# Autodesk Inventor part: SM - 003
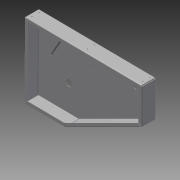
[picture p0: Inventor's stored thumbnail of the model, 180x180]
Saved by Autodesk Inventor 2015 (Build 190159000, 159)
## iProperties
Created: 2007-02
Part Number: SM - 003
Material: Steel
Document SubType Name: Sheet Metal
Designer: Autodesk, Inc.
Mass: 16124.5 g
Surface Area: 13619.8 cm^2
Volume: 2054.07 cm^3
Density: 7.85 g/cm^3
Description: Drive Casing
Sheet Metal Rule: Default
Appearance: Steel
Author: Autodesk, Inc.
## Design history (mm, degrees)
sketch "Sketch1"
  geometry: L1 (-191.283, 377.15)-(658.676, 368.784) reference; L2 (658.676, 368.784)-(656.097, 106.765); L3 (656.097, 106.765)-(102.83, -170.662); L4 (102.83, -170.662)-(-196.646, -167.714); L5 (-196.646, -167.714)-(-191.283, 377.15); L6 (-99.694, 136.47)-(-25.616, 266.858); L7 (-20.095, 263.721)-(-94.173, 133.333); L8 (-105.215, 139.606)-(-31.137, 269.995); C1 r 25.4 at (30.661, 24.948); C2 r 15.875 at (514.8, 240.763) reference; C3 r 17.145 at (514.8, 240.763); C4 r 6.35 at (190.203, 181.588); A1 r 6.35 centre (-99.694, 136.47) between (-105.215, 139.606) and (-94.173, 133.333); A2 r 6.35 centre (-25.616, 266.858) between (-20.095, 263.721) and (-31.137, 269.995); 1 further point
  constraints: 14 end point, 5 centre point, 4 point on circle, 4 tangent, 3 coincident, 2 perpendicular, 1 parallel, 1 other
  dimensions: "d0" = 1.27 radial gap between concentric circles of C3 C2; "d1" = 12.7 diameter of A2; "d2" = 12.7 diameter of A1 (= d1); "d3" = 12.7 diameter of C4
  node "Reference2"
  node "Reference3"
node "Face1"
node "Flange1"
node "Flange2"
node "Flange3"
feature "Corner4" dims "d34" = 12.192 (= CornerReliefSize), "d35" = 3.048 (= BendRadius), "d36" = 3.048 (= Thickness), "d37" = 0, "Thickness" = 3.048
node "Flange4"
feature "Corner6" dims "d49" = 12.192 (= CornerReliefSize), "d50" = 3.048 (= BendRadius), "d51" = 3.048 (= Thickness), "d52" = 0, "Thickness" = 3.048
node "Flange5"
node "Flange6"
feature "Corner9" dims "d75" = 12.192 (= CornerReliefSize), "d76" = 3.048 (= BendRadius), "d77" = 3.048 (= Thickness), "d78" = 0, "Thickness" = 3.048
feature "Corner10" dims "d79" = 12.192 (= CornerReliefSize), "d80" = 3.048 (= BendRadius), "d81" = 3.048 (= Thickness), "d82" = 0, "Thickness" = 3.048
feature "Corner11" dims "d83" = 12.192 (= CornerReliefSize), "d84" = 3.048 (= BendRadius), "d85" = 3.048 (= Thickness), "d86" = 0, "Thickness" = 3.048
hole "Hole1" diameter "d89" = 6.7564; stored, may be unused: countersink angle "d93" = 82 deg, drill point angle "d95" = 118 deg; dims "d87" = 19.05, "d88" = 19.05, "d90" = 12.7, "d91" = 11.1252, "d92" = 6.35, "d94" = 3.048 (= Thickness)
pattern_linear "Rectangular Pattern1" dims "d98" = 50.8, "d101" = 401.32
hole "Hole2" diameter "d104" = 3.683; stored, may be unused: countersink angle "d108" = 82 deg, drill point angle "d110" = 118 deg; dims "d102" = 9.525, "d103" = 25.4, "d105" = 12.7, "d106" = 9.525, "d107" = 6.35, "d109" = 3.048 (= Thickness)
hole "Hole3" diameter "d113" = 3.683; stored, may be unused: countersink angle "d117" = 82 deg, drill point angle "d119" = 118 deg; dims "d111" = 9.525, "d112" = 31.75, "d114" = 12.7, "d115" = 9.525, "d116" = 6.35, "d118" = 3.048 (= Thickness)
hole "Hole4" diameter "d122" = 3.683; stored, may be unused: countersink angle "d126" = 82 deg, drill point angle "d128" = 118 deg; dims "d120" = 9.525, "d121" = 31.75, "d123" = 12.7, "d124" = 9.525, "d125" = 6.35, "d127" = 3.048 (= Thickness)
hole "Hole5" diameter "d131" = 3.683; stored, may be unused: countersink angle "d135" = 82 deg, drill point angle "d137" = 118 deg; dims "d129" = 9.525, "d130" = 15.875, "d132" = 12.7, "d133" = 9.525, "d134" = 6.35, "d136" = 3.048 (= Thickness)
hole "Hole6" diameter "d140" = 3.683; stored, may be unused: countersink angle "d144" = 82 deg, drill point angle "d146" = 118 deg; dims "d138" = 9.525, "d139" = 31.75, "d141" = 12.7, "d142" = 9.525, "d143" = 6.35, "d145" = 3.048 (= Thickness)
pattern_linear "Rectangular Pattern2" dims "d149" = 483.4382
pattern_linear "Rectangular Pattern3" dims "d152" = 251.5362
pattern_linear "Rectangular Pattern4" dims "d155" = 574.8782
pattern_linear "Rectangular Pattern5" dims "d158" = 782.193
pattern_linear "Rectangular Pattern6" dims "d161" = 204.4954
body "Solid1"
face "Plate1" dims "Thickness" = 3.048
sketch "Sketch2"
  geometry: L1 through (-425, 0) direction (1, -7.25e-35); L2 through (0, 50.8) direction (0, 1); L3 (0, 101.6)-(-850, 101.6); L4 (-850, 101.6)-(-850, 0)
  constraints: 6 end point, 1 horizontal, 1 perpendicular, 1 vertical
face "Plate2" dims "d5" = 3.048 (= BendReliefWidth), "d6" = 1.524 (= BendReliefDepth), "d7" = 6.096 (= MinimumRemnant), "d8" = 3.048 (= BendRadius), "d9" = 101.6, "d10" = 90 deg, "d11" = 3.048 (= BendRadius), "d12" = 12.192 (= CornerReliefSize), "d13" = 3.048 (= Thickness), "d162" = 3.048 (= JacobiRadiusSize), "SeamGap" = 0.00508, "Thickness" = 3.048
bend "Bend1" dims "d5" = 3.048 (= BendReliefWidth), "d6" = 1.524 (= BendReliefDepth), "d7" = 6.096 (= MinimumRemnant), "d8" = 3.048 (= BendRadius), "d9" = 101.6, "d10" = 90 deg, "d11" = 3.048 (= BendRadius), "SeamGap" = 0.00508, "Thickness" = 3.048
feature "Corner1" dims "d9" = 101.6, "d10" = 90 deg, "d12" = 12.192 (= CornerReliefSize), "d13" = 3.048 (= Thickness), "d162" = 3.048 (= JacobiRadiusSize)
sketch "Sketch3"
  geometry: L1 through (419.776, -4.132) direction (-1, 0.00984); L2 through (-0.125, -12.699) direction (-0.00984, -1); L3 (-0.25, -25.399)-(839.303, -33.662); L4 (839.303, -33.662)-(839.553, -8.264)
  constraints: 6 end point, 1 perpendicular, 2 other
face "Plate3" dims "d14" = 3.048 (= BendReliefWidth), "d15" = 1.524 (= BendReliefDepth), "d16" = 6.096 (= MinimumRemnant), "d17" = 3.048 (= BendRadius), "d18" = 25.4, "d19" = 90 deg, "d20" = 3.048 (= BendRadius), "d21" = 12.192 (= CornerReliefSize), "d22" = 3.048 (= Thickness), "d163" = 3.048 (= JacobiRadiusSize), "SeamGap" = 0.00508, "Thickness" = 3.048
bend "Bend2" dims "d14" = 3.048 (= BendReliefWidth), "d15" = 1.524 (= BendReliefDepth), "d16" = 6.096 (= MinimumRemnant), "d17" = 3.048 (= BendRadius), "d18" = 25.4, "d19" = 90 deg, "d20" = 3.048 (= BendRadius), "SeamGap" = 0.00508, "Thickness" = 3.048
feature "Corner2" dims "d18" = 25.4, "d19" = 90 deg, "d21" = 12.192 (= CornerReliefSize), "d22" = 3.048 (= Thickness), "d163" = 3.048 (= JacobiRadiusSize)
sketch "Sketch4"
  geometry: L1 (-0.224, -22.736)-(-2.492, -253.169); L2 (-2.492, -253.169)-(-27.891, -252.919); L3 (-27.891, -252.919)-(-25.623, -22.486); L4 (-25.623, -22.486)-(-0.224, -22.736)
  constraints: 8 end point
face "Plate4" dims "d23" = 3.048 (= BendReliefWidth), "d24" = 1.524 (= BendReliefDepth), "d25" = 6.096 (= MinimumRemnant), "d26" = 3.048 (= BendRadius), "d27" = 0, "d28" = 2.54, "d29" = 25.4, "d30" = 90 deg, "d31" = 3.048 (= BendRadius), "d32" = 12.192 (= CornerReliefSize), "d33" = 3.048 (= Thickness), "d164" = 3.048 (= JacobiRadiusSize), "SeamGap" = 0.00508, "Thickness" = 3.048
bend "Bend3" dims "d23" = 3.048 (= BendReliefWidth), "d24" = 1.524 (= BendReliefDepth), "d25" = 6.096 (= MinimumRemnant), "d26" = 3.048 (= BendRadius), "d29" = 25.4, "d30" = 90 deg, "d31" = 3.048 (= BendRadius), "SeamGap" = 0.00508, "Thickness" = 3.048
feature "Corner3" dims "d29" = 25.4, "d30" = 90 deg, "d32" = 12.192 (= CornerReliefSize), "d33" = 3.048 (= Thickness), "d164" = 3.048 (= JacobiRadiusSize)
sketch "Sketch5"
  geometry: L1 (-17.717, -8.884)-(-547.946, -274.759); L2 (-547.946, -274.759)-(-559.332, -252.054); L3 (-559.332, -252.054)-(-29.102, 13.821); L4 (-29.102, 13.821)-(-17.717, -8.884)
  constraints: 8 end point
face "Plate5" dims "d38" = 3.048 (= BendReliefWidth), "d39" = 1.524 (= BendReliefDepth), "d40" = 6.096 (= MinimumRemnant), "d41" = 3.048 (= BendRadius), "d42" = 0, "d43" = 2.54, "d44" = 25.4, "d45" = 90 deg, "d46" = 3.048 (= BendRadius), "d47" = 12.192 (= CornerReliefSize), "d48" = 3.048 (= Thickness), "d165" = 3.048 (= JacobiRadiusSize), "SeamGap" = 0.00508, "Thickness" = 3.048
bend "Bend4" dims "d38" = 3.048 (= BendReliefWidth), "d39" = 1.524 (= BendReliefDepth), "d40" = 6.096 (= MinimumRemnant), "d41" = 3.048 (= BendRadius), "d44" = 25.4, "d45" = 90 deg, "d46" = 3.048 (= BendRadius), "SeamGap" = 0.00508, "Thickness" = 3.048
feature "Corner5" dims "d44" = 25.4, "d45" = 90 deg, "d47" = 12.192 (= CornerReliefSize), "d48" = 3.048 (= Thickness), "d165" = 3.048 (= JacobiRadiusSize)
sketch "Sketch6"
  geometry: L1 (-9.792, 0.096)-(-291.968, 2.874); L2 (-291.968, 2.874)-(-291.718, 28.273); L3 (-291.718, 28.273)-(-9.542, 25.495); L4 (-9.542, 25.495)-(-9.792, 0.096)
  constraints: 8 end point
face "Plate6" dims "d53" = 3.048 (= BendReliefWidth), "d54" = 1.524 (= BendReliefDepth), "d55" = 6.096 (= MinimumRemnant), "d56" = 3.048 (= BendRadius), "d57" = 0, "d58" = 2.54, "d59" = 25.4, "d60" = 90 deg, "d61" = 3.048 (= BendRadius), "d62" = 12.192 (= CornerReliefSize), "d63" = 3.048 (= Thickness), "d166" = 3.048 (= JacobiRadiusSize), "SeamGap" = 0.00508, "Thickness" = 3.048
bend "Bend5" dims "d53" = 3.048 (= BendReliefWidth), "d54" = 1.524 (= BendReliefDepth), "d55" = 6.096 (= MinimumRemnant), "d56" = 3.048 (= BendRadius), "d59" = 25.4, "d60" = 90 deg, "d61" = 3.048 (= BendRadius), "SeamGap" = 0.00508, "Thickness" = 3.048
feature "Corner7" dims "d59" = 25.4, "d60" = 90 deg, "d62" = 12.192 (= CornerReliefSize), "d63" = 3.048 (= Thickness), "d166" = 3.048 (= JacobiRadiusSize)
sketch "Sketch7"
  geometry: L1 (0.224, 22.736)-(5.037, 511.722); L2 (5.037, 511.722)-(30.436, 511.472); L3 (30.436, 511.472)-(25.623, 22.486); L4 (25.623, 22.486)-(0.224, 22.736)
  constraints: 8 end point
face "Plate7" dims "d64" = 3.048 (= BendReliefWidth), "d65" = 1.524 (= BendReliefDepth), "d66" = 6.096 (= MinimumRemnant), "d67" = 3.048 (= BendRadius), "d68" = 2.54, "d69" = 2.54, "d70" = 25.4, "d71" = 90 deg, "d72" = 3.048 (= BendRadius), "d73" = 12.192 (= CornerReliefSize), "d74" = 3.048 (= Thickness), "d167" = 3.048 (= JacobiRadiusSize), "SeamGap" = 0.00508, "Thickness" = 3.048
bend "Bend6" dims "d64" = 3.048 (= BendReliefWidth), "d65" = 1.524 (= BendReliefDepth), "d66" = 6.096 (= MinimumRemnant), "d67" = 3.048 (= BendRadius), "d70" = 25.4, "d71" = 90 deg, "d72" = 3.048 (= BendRadius), "SeamGap" = 0.00508, "Thickness" = 3.048
feature "Corner8" dims "d70" = 25.4, "d71" = 90 deg, "d73" = 12.192 (= CornerReliefSize), "d74" = 3.048 (= Thickness), "d167" = 3.048 (= JacobiRadiusSize)
other parameters: "BendRadius" = 3.048 (= Thickness), "BendReliefWidth" = 3.048 (= Thickness), "BendReliefDepth" = 1.524 (= 0.5 x Thickness), "CornerReliefSize" = 12.192 (= 4 x Thickness), "MinimumRemnant" = 6.096 (= 2 x Thickness), "TransitionRadius" = 3.048 (= BendRadius), "JacobiRadiusSize" = 3.048 (= Thickness), "d4" = 3.048 (= BendRadius), "GapSize" = 3.048 (= Thickness)
